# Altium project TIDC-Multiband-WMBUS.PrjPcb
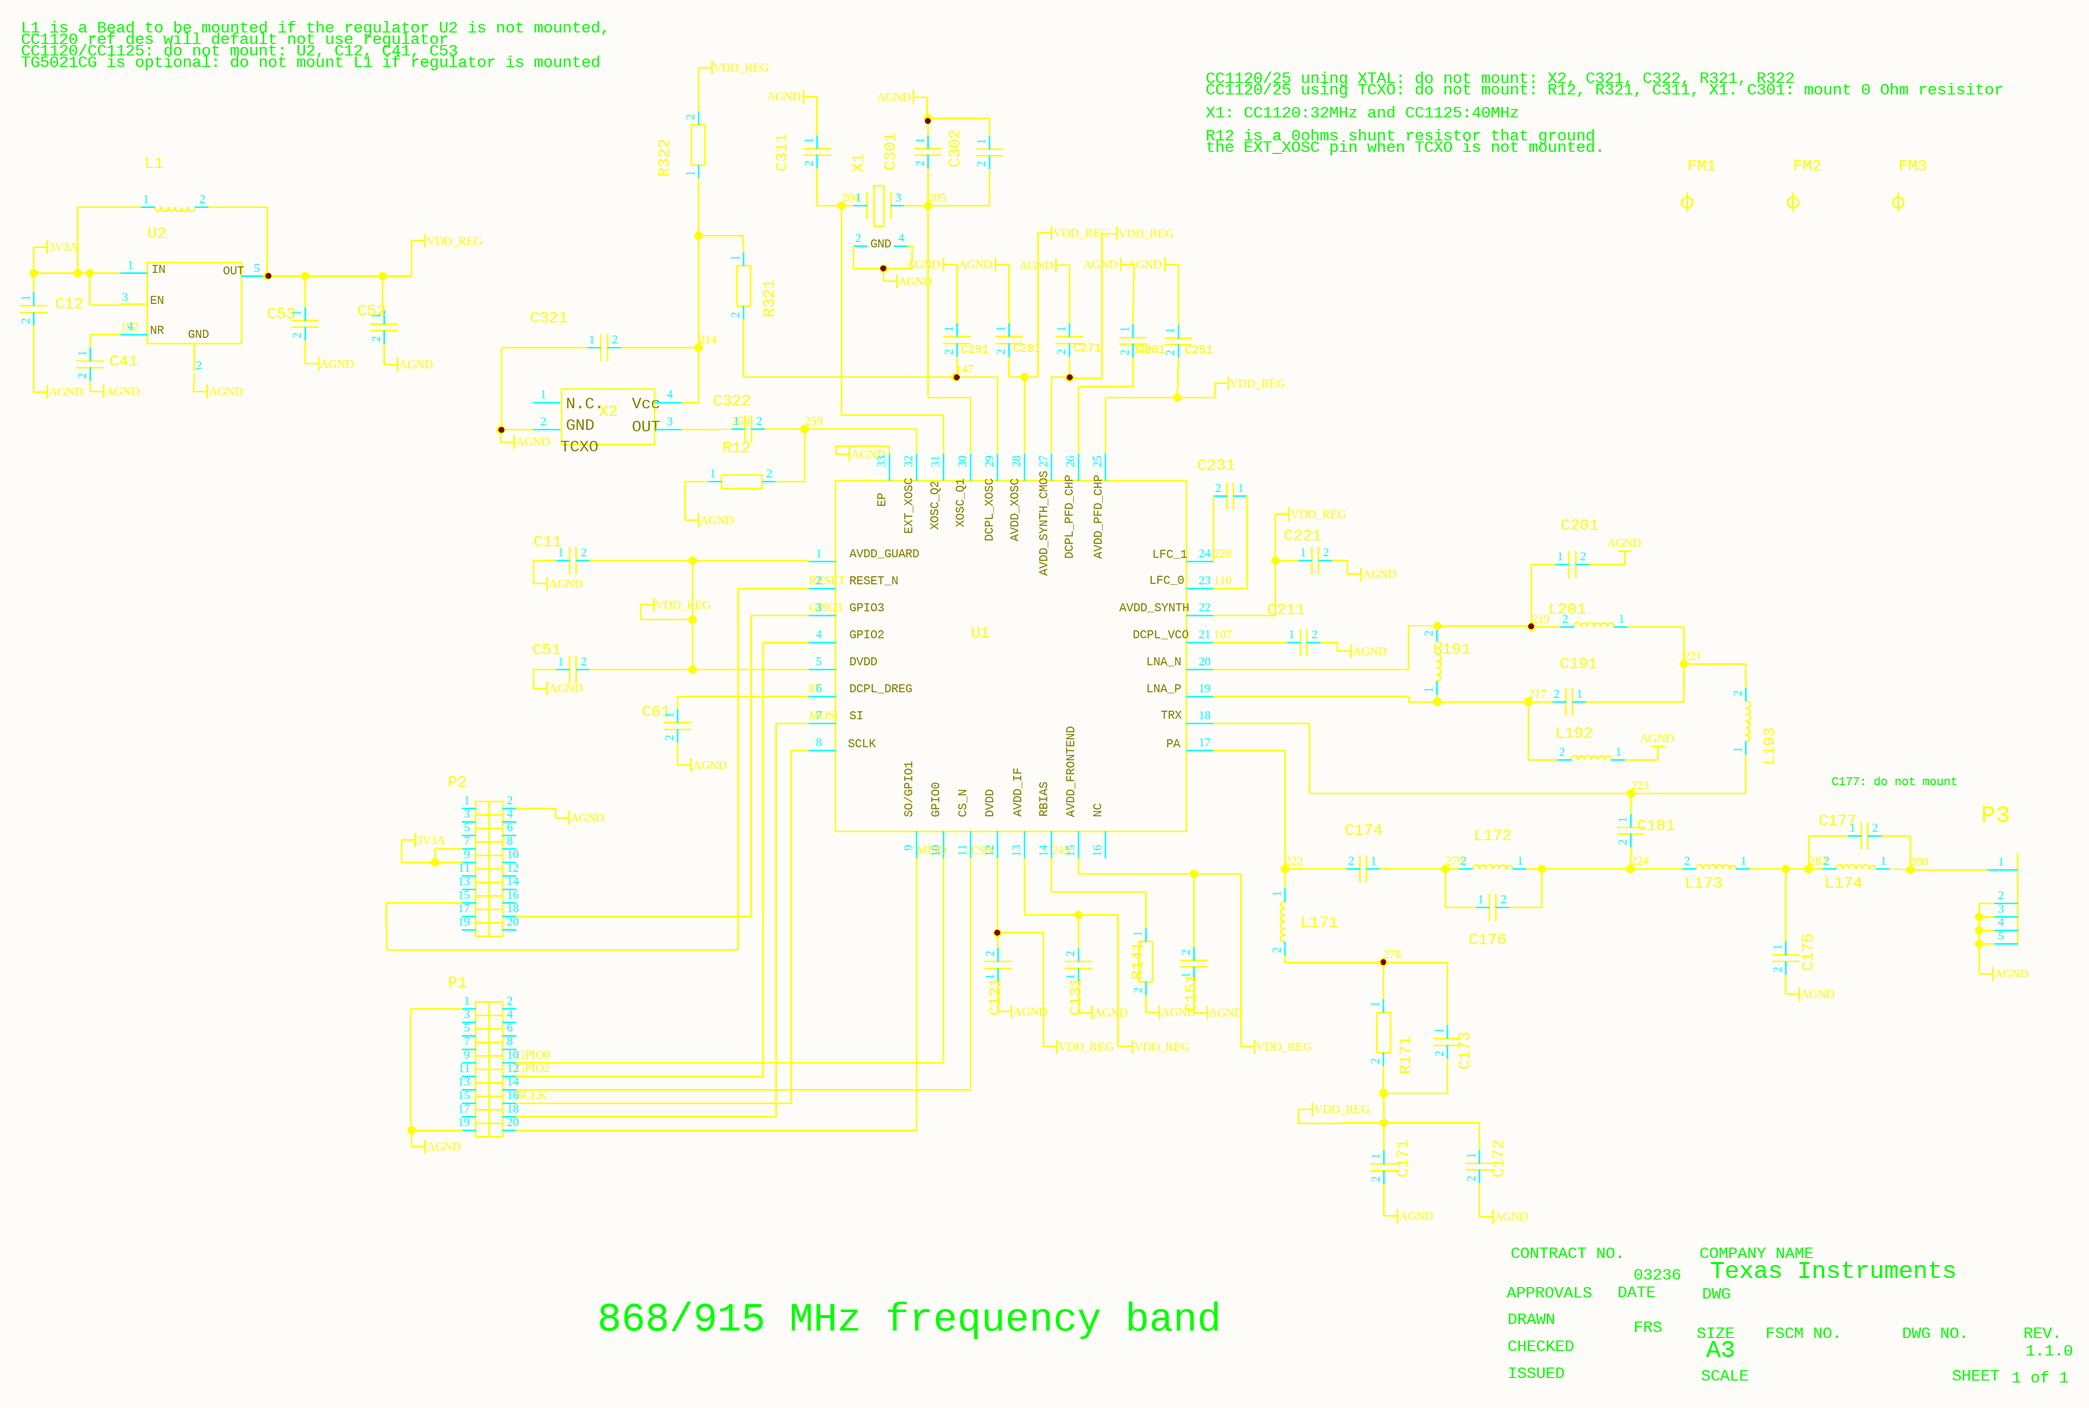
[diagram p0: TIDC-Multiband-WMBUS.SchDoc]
1 sheet, 57 parts. Net scope: global (net labels, ports and power ports of the same name join across sheets).
Board file: TIDC-Multiband-WMBUS.PcbDoc

## Sheet TIDC-Multiband-WMBUS.SchDoc
size 999 x 999 mm

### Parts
C11  *  (value not drawn)
C12  *  (value not drawn)
C41  *  (value not drawn)
C51  *  (value not drawn)
C52  *  (value not drawn)
C53  *  (value not drawn)
C61  *  (value not drawn)
C121  *  (value not drawn)
C131  *  (value not drawn)
C151  *  (value not drawn)
C171  *  (value not drawn)
C172  *  (value not drawn)
C173  *  (value not drawn)
C174  *  (value not drawn)
C175  *  (value not drawn)
C176  *  (value not drawn)
C177  *  (value not drawn)
C181  *  (value not drawn)
C191  *  (value not drawn)
C201  *  (value not drawn)
C211  *  (value not drawn)
C221  *  (value not drawn)
C231  *  (value not drawn)
C251  *  (value not drawn)
C261  *  (value not drawn)
C271  *  (value not drawn)
C281  *  (value not drawn)
C291  *  (value not drawn)
C301  *  (value not drawn)
C302  *  (value not drawn)
C311  *  (value not drawn)
C321  *  (value not drawn)
C322  *  (value not drawn)
FM1  *  (value not drawn)
FM2  *  (value not drawn)
FM3  *  (value not drawn)
L1  *  (value not drawn)
L171  *  (value not drawn)
L172  *  (value not drawn)
L173  *  (value not drawn)
L174  *  (value not drawn)
L191  *  (value not drawn)
L192  *  (value not drawn)
L193  *  (value not drawn)
L201  *  (value not drawn)
P1  *  (value not drawn)
P2  *  (value not drawn)
P3  *  (value not drawn)
R12  *  (value not drawn)
R141  *  (value not drawn)
R171  *  (value not drawn)
R321  *  (value not drawn)
R322  *  (value not drawn)
U1  *  (value not drawn)
U2  *  (value not drawn)
X1  *  (value not drawn)
X2  *  (value not drawn)

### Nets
3V3A: C12.1 L1.1 P2.7 P2.9 U2.1 U2.3
AGND: C11.1 C12.2 C41.2 C51.1 C52.2 C53.2 C61.2 C121.1 C131.1 C151.1 C171.2 C172.2 C175.2 C201.2 C211.2 C221.2 C251.1 C261.1 C271.1 C281.1 C291.1 C301.1 C302.1 C311.1 C321.1 L192.1 P1.1 P1.19 P2.2 P3.2 P3.3 P3.4 P3.5 R12.1 R141.2 U1.33 U2.2 X1.2 X1.4 X2.2
VDD_REG: C11.2 C51.2 C52.1 C53.1 C121.2 C131.2 C151.2 C171.1 C172.1 C173.2 C221.1 C251.2 C271.2 C281.2 L1.2 R171.2 R322.2 U1.1 U1.5 U1.12 U1.13 U1.15 U1.22 U1.25 U1.27 U1.28 U2.5
87: C61.1 U1.6
107: C211.1 U1.21
110: C231.1 U1.23
147: C291.2 R321.2 U1.29
149: C261.2 U1.26
192: C41.1 U2.4
204: C311.2 U1.31 X1.1
205: C301.2 C302.2 U1.30 X1.3
214: C321.2 R321.1 R322.1 X2.4
217: C191.2 L191.1 L192.2 U1.19
219: C201.1 L191.2 L201.2 U1.20
221: C191.1 L193.2 L201.1
222: C174.2 L171.1 U1.17
223: C181.1 L193.1 U1.18
224: C176.2 C181.2 L172.1 L173.2
228: C231.2 U1.24
243: R141.1 U1.14
258: C322.1 X2.3
259: C322.2 R12.2 U1.32
278: C173.1 L171.2 R171.1
279: C174.1 C176.1 L172.2
280: C177.2 L174.1 P3.1
282: C175.1 C177.1 L173.1 L174.2
CSN: P1.14 U1.11
GPIO0: P1.10 U1.10
GPIO2: P1.12 U1.4
GPIO3: P2.18 U1.3
MISO: P1.20 U1.9
MOSI: P1.18 U1.7
RESET: P2.15 U1.2
SCLK: P1.16 U1.8

Not connected (* = marked no-connect by the designer): FM1 1; FM2 1; FM3 1; P1 2 3 4 5 6 7 8 9 11 13 15 17; P2 1 3 4 5 6 8 10 11 12 13 14 16 17 19 20; U1 16; X2 1

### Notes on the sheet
- CC1120/CC1125: do not mount: U2, C12, C41, C53
- CC1120 ref des will default not use regulator
- L1 is a Bead to be mounted if the regulator U2 is not mounted,
- TG5021CG is optional: do not mount L1 if regulator is mounted
- X1: CC1120:32MHz and CC1125:40MHz
- CC1120/25 using TCXO: do not mount: R12, R321, C311, X1. C301: mount 0 Ohm resisitor
- CC1120/25 uning XTAL: do not mount: X2, C321, C322, R321, R322
- the EXT_XOSC pin when TCXO is not mounted.
- R12 is a 0ohms shunt resistor that ground
- (near C177) C177: do not mount
- CONTRACT NO.
- COMPANY NAME
- 868/915 MHz frequency band
- APPROVALS
- DRAWN
- DATE
- 03236
- FRS
- SIZE
- DWG
- Texas Instruments
- FSCM NO.
- DWG NO.
- REV.
- ISSUED
- CHECKED
- SCALE
- A3
- SHEET
- 1 of 1
- 1.1.0

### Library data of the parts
C11 C51 C121 C131 C151 C221 C251 C261 C271 C281 C291 = C_47N_0402_X7R_K_25: Capacitor 0402; pick_and_place: P
C12 C321 = C_100N_0402_X5R_K_10: Capacitor 0402; pick_and_place: P
C41 C171 C211 = C_10N_0402_X7R_K_25: Capacitor 0402; pick_and_place: P
C52 = C_2U2_0603_X5R_K_10: Capacitor 0603; pick_and_place: P
C53 C177 C302 = C_0402: Capacitor 0402, general; pick_and_place: P
C61 = C_220N_0402_X5R_K_10: Capacitor 0402; pick_and_place: P
C172 = C_100P_0402_NP0_J_50: Capacitor 0402; pick_and_place: P
C173 = C_33P_0402_NP0_J_50: Capacitor 0402; pick_and_place: P
C174 C301 C311 = C_15P_0402_NP0_J_50: Capacitor, 0402; pick_and_place: P
C175 = C_3P0_0402_NP0_C_50: Capacitor 0402; pick_and_place: P
C176 = C_1P0_0402_NP0_B_50: Capacitor, 1p, 0402, NP0, +/-0.1pF 50V; pick_and_place: P
C181 = C_2P2_0402_NP0_C_50: Capacitor 0402; pick_and_place: P
C191 C201 = C_3P3_0402_NP0_C_50: Capacitor 0402; pick_and_place: P
C231 = C_1N8_0402_U2J_J_10: Capacitor 0402; pick_and_place: P
C322 = C_22P_0402_NP0_J_50: Capacitor 0402; pick_and_place: P
FM1-FM3 = FIDUCIAL_MARK: Fiducial mark; pick_and_place: P
L1 = L_BEAD_102_0402: EMI filter bead, BLM15HG102SN1D; pick_and_place: P
L171 = L_10N_0402_J_LQW: Inductor, 10nH, 0402, Wire-wound type, +/-5 %; pick_and_place: P
L172 = L_7N5_0402_G_LQW: Inductor, 7.5nH, 0402, Wire-wound type, +/-2%; pick_and_place: P
L173 = L_18N_0402_J_LQW: Inductor, 18nH, 0402, Wire-wound type, +/- 5%; pick_and_place: P
L174 L192 L193 L201 = L_12N_0402_J_LQW: Inductor, 12nH, 0402, Wire-wound type, +/-5 %; pick_and_place: P
L191 = L_15N_0402_J_LQW: Inductor, 15nH, 0402, Wire-wound type, +/- 5%; pick_and_place: P
P1 P2 = SMD_SOCKET_2X10: SMD pinrow socket, .050 spacing; pick_and_place: P; link Datasheet: G:\06_TEKNISK\064_Datasheets\Samtec\SFM_SM.pdf
P3 = SMA_SMD: Surface-mount SMA, straight; pick_and_place: P
R12 R321 = R_0402: Resistor 0402, general; pick_and_place: P
R141 = R_56K_0402_F: Resistor 0402; pick_and_place: P
R171 = R_10_0402_J: Resistor 0402; pick_and_place: P
R322 = R_0_0402: Resistor, 0402; pick_and_place: P
U1 = CC112X: High performance narrow band tranceiver; pick_and_place: P
U2 = TPS79930: LDO 3V low noise; pick_and_place: P
X1 = X_32.000/10/20/60/10: Epson Toyocom FA128 32 MHz 2x1.6mm 10 pF, -40/85C, Q22FA1280009200; pick_and_place: P
X2 = TG_5021CG: EpsonToyocom miniature size TCXO 2.5x2.0mm; pick_and_place: P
